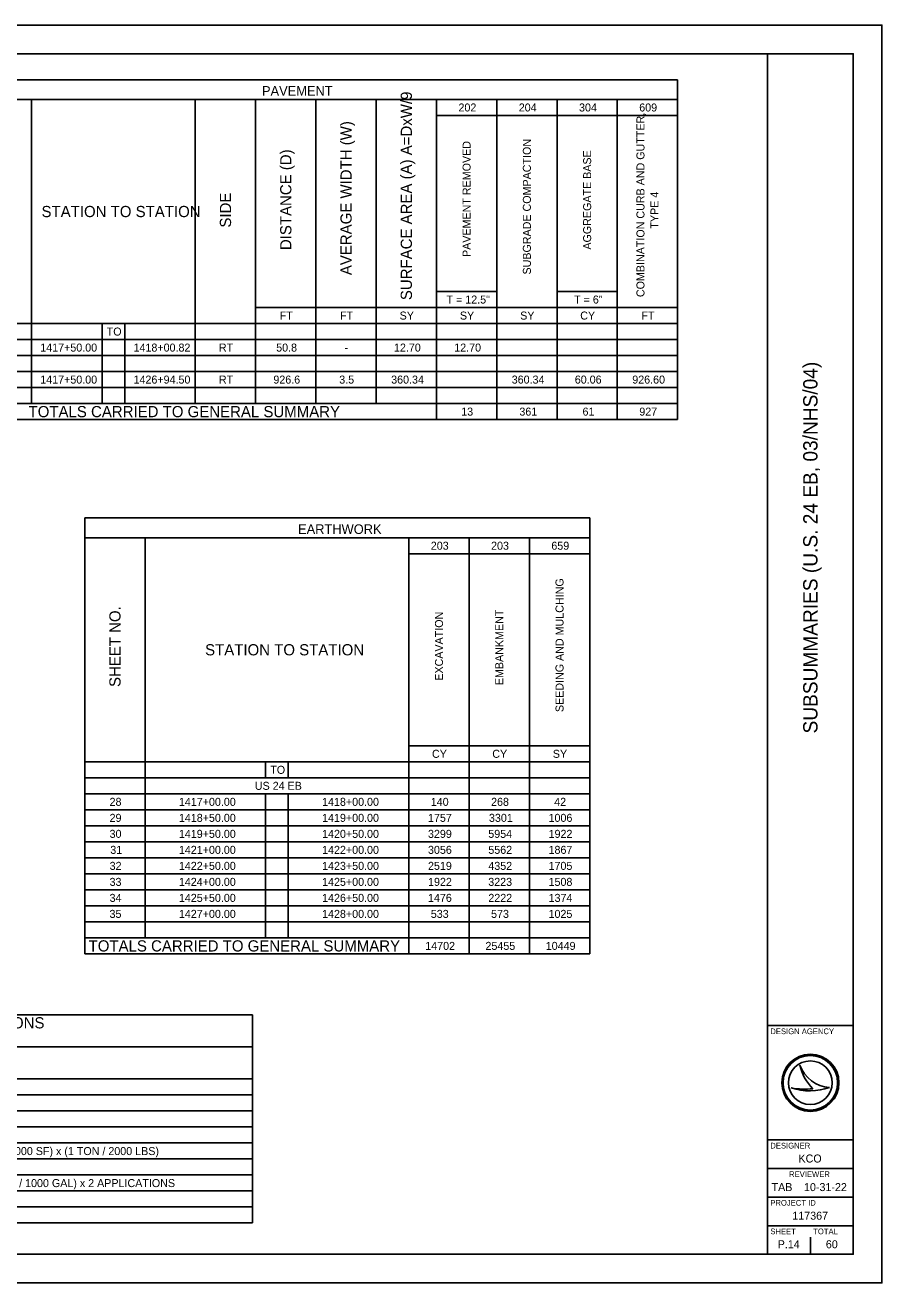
# Model space of a CAD drawing. Extents: x 0 to 34, y 0 to 22.
# Drawn here: x 19.02 to 34, y 0 to 22 of the extents above; entities that cross this region are included whole.
import ezdxf

# ---------------------------------------------------------------- set-up
doc = ezdxf.new("R2010")
doc.units = 0
for name, color, linetype in [('SH_Border', 7, 'Continuous'), ('SH_Cut_Line', 7, 'Continuous'), ('SH_Data', 7, 'Continuous'), ('SH_Text', 7, 'Continuous')]:
    doc.layers.add(name, color=color, linetype=linetype)

msp = doc.modelspace()

# ---------------------------------------------------------------- linework, layer by layer
at = {"layer": 'SH_Border'}
for p, q in [((32, 0.5), (32, 21.5)), ((32, 4.5), (33.5, 4.5)), ((32, 2.5), (33.5, 2.5)), ((32, 2), (33.5, 2)), ((32, 1.5), (33.5, 1.5)), ((32, 1), (33.5, 1))]:
    msp.add_line(p, q, dxfattribs=at)
msp.add_lwpolyline([(1.5, 21.5), (33.5, 21.5), (33.5, 0.5), (1.5, 0.5)], close=True, dxfattribs=at)
at = {"layer": 'SH_Cut_Line'}
msp.add_lwpolyline([(0, 0), (34, 0), (34, 22), (0, 22)], close=True, dxfattribs=at)
at = {"layer": 'SH_Data'}
for p, q in [((32.567, 3.81), (32.567, 3.81)), ((32.417, 3.41), (32.417, 3.41)), ((32.75, 3.5), (32.75, 3.5)), ((33.087, 3.419), (33.087, 3.419)), ((32.375, 0.675), (32.375, 0.675)), ((32.75, 0.5), (32.75, 0.8))]:
    msp.add_line(p, q, dxfattribs=at)
for radius in [0.5, 0.477, 0.477, 0.382]:
    msp.add_circle((32.75, 3.5), radius, dxfattribs=at)
for centre, radius, start, end in [((33.116, 3.998), 0.58, 198.9257, 198.9319), ((33.347, 3.97), 0.796, 191.6379, 191.6421), ((33.116, 3.998), 0.58, 198.9319, 267.1657), ((33.347, 3.97), 0.796, 191.6421, 226.0947), ((32.739, 4.37), 1.013, 251.4576, 290.0832), ((32.648, 4.654), 1.266, 259.4964, 259.4995), ((32.739, 4.37), 1.013, 251.4527, 251.4576), ((32.648, 4.654), 1.266, 259.4995, 276.6672)]:
    msp.add_arc(centre, radius, start, end, dxfattribs=at)
at = {"layer": 'SH_Text'}
for p, q in [((17.021, 21.046), (30.428, 21.046)), ((30.428, 21.046), (30.428, 15.1)), ((17.021, 20.7), (30.428, 20.7)), ((19.13, 20.7), (19.13, 15.38)), ((21.995, 20.7), (21.995, 15.38)), ((23.05, 20.7), (23.05, 15.38)), ((24.104, 20.7), (24.104, 15.38)), ((25.158, 20.7), (25.158, 15.38)), ((26.212, 20.7), (26.212, 15.1)), ((27.266, 20.7), (27.266, 15.1)), ((28.32, 20.7), (28.32, 15.1)), ((29.374, 20.7), (29.374, 15.1)), ((26.212, 20.42), (30.428, 20.42)), ((26.212, 17.34), (27.266, 17.34)), ((28.32, 17.34), (29.374, 17.34)), ((23.05, 17.06), (30.428, 17.06)), ((17.021, 16.78), (30.428, 16.78)), ((20.365, 16.78), (20.365, 15.38)), ((20.76, 16.78), (20.76, 15.38)), ((17.021, 16.5), (30.428, 16.5)), ((17.021, 16.22), (30.428, 16.22)), ((17.021, 15.94), (30.428, 15.94)), ((17.021, 15.66), (30.428, 15.66)), ((17.021, 15.38), (30.428, 15.38)), ((17.021, 15.1), (30.428, 15.1)), ((20.063, 13.38), (28.891, 13.38)), ((20.063, 13.38), (20.063, 5.754)), ((28.891, 13.38), (28.891, 5.754)), ((20.063, 13.034), (28.891, 13.034)), ((21.117, 13.034), (21.117, 6.034)), ((25.729, 13.034), (25.729, 5.754)), ((26.783, 13.034), (26.783, 5.754)), ((27.837, 13.034), (27.837, 5.754)), ((25.729, 12.754), (28.891, 12.754)), ((25.729, 9.394), (28.891, 9.394)), ((20.063, 9.114), (28.891, 9.114)), ((23.225, 9.114), (23.225, 8.834)), ((23.62, 9.114), (23.62, 8.834)), ((20.063, 8.834), (28.891, 8.834)), ((20.063, 8.554), (28.891, 8.554)), ((23.225, 8.554), (23.225, 6.034)), ((23.62, 8.554), (23.62, 6.034)), ((20.063, 8.274), (28.891, 8.274)), ((20.063, 7.994), (28.891, 7.994)), ((20.063, 7.714), (28.891, 7.714)), ((20.063, 7.434), (28.891, 7.434)), ((20.063, 7.154), (28.891, 7.154)), ((20.063, 6.874), (28.891, 6.874)), ((20.063, 6.594), (28.891, 6.594)), ((20.063, 6.314), (28.891, 6.314)), ((20.063, 6.034), (28.891, 6.034)), ((20.063, 5.754), (28.891, 5.754)), ((9.998, 4.689), (22.994, 4.689)), ((22.994, 4.689), (22.994, 1.049)), ((9.998, 4.129), (22.994, 4.129)), ((9.998, 3.569), (22.994, 3.569)), ((9.998, 3.289), (22.994, 3.289)), ((9.998, 3.009), (22.994, 3.009)), ((9.998, 2.729), (22.994, 2.729)), ((9.998, 2.449), (22.994, 2.449)), ((9.998, 2.169), (22.994, 2.169)), ((9.998, 1.889), (22.994, 1.889)), ((9.998, 1.609), (22.994, 1.609)), ((9.998, 1.329), (22.994, 1.329)), ((9.998, 1.049), (22.994, 1.049))]:
    msp.add_line(p, q, dxfattribs=at)

# ---------------------------------------------------------------- texts
at = {"layer": 'SH_Data'}
msp.add_text('SUBSUMMARIES (U.S. 24 EB, 03/NHS/04)', height=0.25, rotation=90, dxfattribs=at).set_placement((32.875, 9.61))
for s, height, p in [('DESIGN AGENCY', 0.1, (32.05, 4.35)), ('DESIGNER', 0.1, (32.05, 2.35)), ('KCO', 0.14, (32.542, 2.105)), ('REVIEWER', 0.1, (32.378, 1.85)), ('TAB', 0.14, (32.072, 1.605)), ('10-31-22', 0.14, (32.639, 1.605)), ('PROJECT ID', 0.1, (32.05, 1.35)), ('117367', 0.14, (32.435, 1.105)), ('SHEET', 0.1, (32.05, 0.85)), ('TOTAL', 0.1, (32.8, 0.85)), ('P.14', 0.14, (32.179, 0.605)), ('60', 0.14, (33.021, 0.605))]:
    msp.add_text(s, height=height, dxfattribs=at).set_placement(p)
at = {"layer": 'SH_Text'}
for s, height, p in [('PAVEMENT', 0.168, (23.161, 20.766)), ('202', 0.14, (26.597, 20.49)), ('204', 0.14, (27.651, 20.49)), ('304', 0.14, (28.705, 20.49)), ('609', 0.14, (29.758, 20.49)), ('STATION TO STATION', 0.196, (19.306, 18.642)), ('T = 12.5"', 0.14, (26.388, 17.13)), ('T = 6"', 0.14, (28.619, 17.13)), ('FT', 0.14, (23.471, 16.85)), ('FT', 0.14, (24.525, 16.85)), ('SY', 0.14, (25.568, 16.85)), ('SY', 0.14, (26.622, 16.85)), ('SY', 0.14, (27.676, 16.85)), ('CY', 0.14, (28.726, 16.85)), ('FT', 0.14, (29.796, 16.85)), ('TO', 0.14, (20.446, 16.57)), ('1417+50.00', 0.14, (19.284, 16.29)), ('1418+00.82', 0.14, (20.915, 16.29)), ('RT', 0.14, (22.408, 16.29)), ('50.8', 0.14, (23.409, 16.29)), ('-', 0.14, (24.604, 16.29)), ('12.70', 0.14, (25.469, 16.29)), ('12.70', 0.14, (26.523, 16.29)), ('1417+50.00', 0.14, (19.284, 15.73)), ('1426+94.50', 0.14, (20.915, 15.73)), ('RT', 0.14, (22.408, 15.73)), ('926.6', 0.14, (23.36, 15.73)), ('3.5', 0.14, (24.512, 15.73)), ('360.34', 0.14, (25.42, 15.73)), ('360.34', 0.14, (27.528, 15.73)), ('60.06', 0.14, (28.631, 15.73)), ('926.60', 0.14, (29.636, 15.73)), ('TOTALS CARRIED TO GENERAL SUMMARY', 0.196, (19.079, 15.142)), ('13', 0.14, (26.645, 15.17)), ('361', 0.14, (27.662, 15.17)), ('61', 0.14, (28.766, 15.17)), ('927', 0.14, (29.759, 15.17)), ('EARTHWORK', 0.168, (23.792, 13.1)), ('203', 0.14, (26.113, 12.824)), ('203', 0.14, (27.167, 12.824)), ('659', 0.14, (28.221, 12.824)), ('STATION TO STATION', 0.196, (22.166, 10.976)), ('CY', 0.14, (26.134, 9.184)), ('CY', 0.14, (27.188, 9.184)), ('SY', 0.14, (28.247, 9.184)), ('TO', 0.14, (23.306, 8.904)), ('US 24 EB', 0.14, (23.036, 8.624)), ('28', 0.14, (20.496, 8.344)), ('1417+00.00', 0.14, (21.708, 8.344)), ('1418+00.00', 0.14, (24.212, 8.344)), ('140', 0.14, (26.113, 8.344)), ('268', 0.14, (27.167, 8.344)), ('42', 0.14, (28.271, 8.344)), ('29', 0.14, (20.496, 8.064)), ('1418+50.00', 0.14, (21.708, 8.064)), ('1419+00.00', 0.14, (24.212, 8.064)), ('1757', 0.14, (26.064, 8.064)), ('3301', 0.14, (27.13, 8.064)), ('1006', 0.14, (28.172, 8.064)), ('30', 0.14, (20.496, 7.784)), ('1419+50.00', 0.14, (21.708, 7.784)), ('1420+50.00', 0.14, (24.212, 7.784)), ('3299', 0.14, (26.064, 7.784)), ('5954', 0.14, (27.118, 7.784)), ('1922', 0.14, (28.173, 7.784)), ('31', 0.14, (20.508, 7.504)), ('1421+00.00', 0.14, (21.708, 7.504)), ('1422+00.00', 0.14, (24.212, 7.504)), ('3056', 0.14, (26.064, 7.504)), ('5562', 0.14, (27.119, 7.504)), ('1867', 0.14, (28.172, 7.504)), ('32', 0.14, (20.497, 7.224)), ('1422+50.00', 0.14, (21.708, 7.224)), ('1423+50.00', 0.14, (24.212, 7.224)), ('2519', 0.14, (26.064, 7.224)), ('4352', 0.14, (27.119, 7.224)), ('1705', 0.14, (28.172, 7.224)), ('33', 0.14, (20.496, 6.944)), ('1424+00.00', 0.14, (21.708, 6.944)), ('1425+00.00', 0.14, (24.212, 6.944)), ('1922', 0.14, (26.065, 6.944)), ('3223', 0.14, (27.118, 6.944)), ('1508', 0.14, (28.172, 6.944)), ('34', 0.14, (20.496, 6.664)), ('1425+50.00', 0.14, (21.708, 6.664)), ('1426+50.00', 0.14, (24.212, 6.664)), ('1476', 0.14, (26.064, 6.664)), ('2222', 0.14, (27.119, 6.664)), ('1374', 0.14, (28.173, 6.664)), ('35', 0.14, (20.495, 6.384)), ('1427+00.00', 0.14, (21.708, 6.384)), ('1428+00.00', 0.14, (24.212, 6.384)), ('533', 0.14, (26.113, 6.384)), ('573', 0.14, (27.167, 6.384)), ('1025', 0.14, (28.172, 6.384)), ('TOTALS CARRIED TO GENERAL SUMMARY', 0.196, (20.129, 5.796)), ('14702', 0.14, (26.016, 5.824)), ('25455', 0.14, (27.069, 5.824)), ('10449', 0.14, (28.123, 5.824)), ('SEEDING AND MULCHING CALCULATIONS', 0.196, (13.998, 4.451)), ('COMMERCIAL FERTILIZER (10449 SY x 9 SF / 1 SY) x (30 LBS / 1000 SF) x (1 TON / 2000 LBS)', 0.14, (13.161, 2.235)), ('WATER (10449 SY x 9 SF / 1 SY) x (300 GAL / 1000 SF) x (1 MGAL / 1000 GAL) x 2 APPLICATIONS', 0.14, (13.161, 1.675))]:
    msp.add_text(s, height=height, dxfattribs=at).set_placement(p)
for s, height, p in [('SURFACE AREA (A) A=DxW/9', 0.196, (25.783, 17.19)), ('AVERAGE WIDTH (W)', 0.196, (24.729, 17.627)), ('COMBINATION CURB AND GUTTER, ', 0.14, (29.849, 17.243)), ('DISTANCE (D)', 0.196, (23.675, 18.065)), ('PAVEMENT REMOVED', 0.14, (26.809, 17.945)), ('SUBGRADE COMPACTION', 0.14, (27.863, 17.638)), ('AGGREGATE BASE', 0.14, (28.917, 18.074)), ('SIDE', 0.196, (22.62, 18.459)), ('TYPE 4', 0.14, (30.094, 18.441)), ('SEEDING AND MULCHING', 0.14, (28.434, 9.984)), ('SHEET NO.', 0.196, (20.688, 10.423)), ('EXCAVATION', 0.14, (26.326, 10.533)), ('EMBANKMENT', 0.14, (27.38, 10.455))]:
    msp.add_text(s, height=height, rotation=90, dxfattribs=at).set_placement(p)

doc.saveas('drawing.dxf')
